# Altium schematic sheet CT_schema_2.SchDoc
size 287 x 169 mm
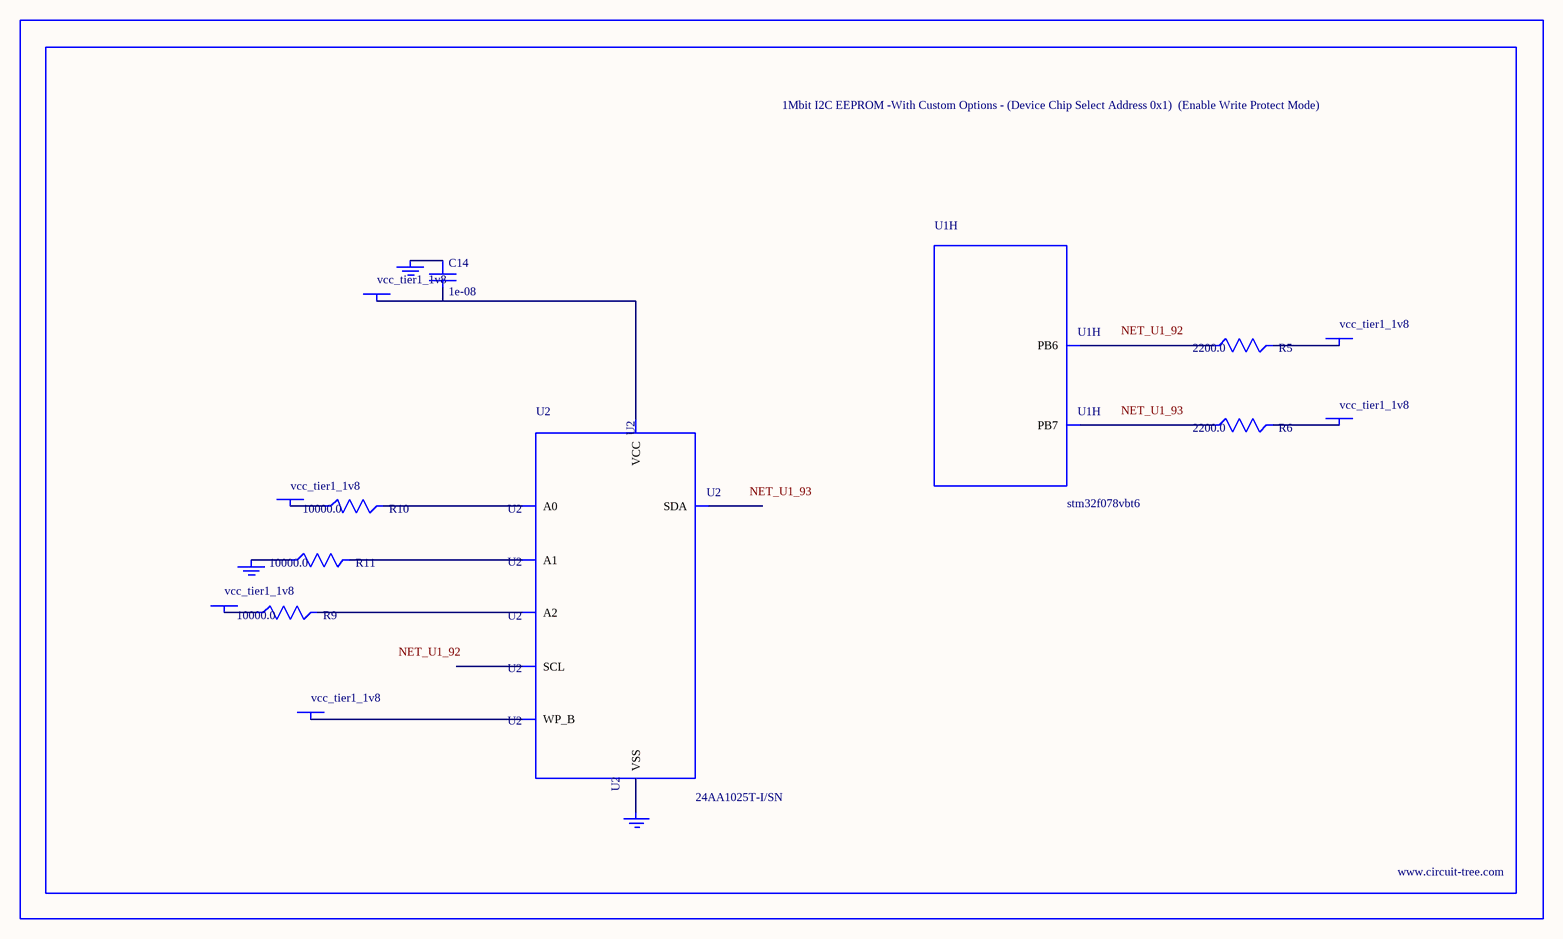
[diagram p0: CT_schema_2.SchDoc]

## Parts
BORDER1  (no value)
C14  1e-08  [C0402]
GND_INSTANCE_1_0  (no value)
GND_INSTANCE_1_1  (no value)
GND_INSTANCE_1_2  (no value)
POWER_INSTANCE_1_0  vcc_tier1_1v8
POWER_INSTANCE_1_1  vcc_tier1_1v8
POWER_INSTANCE_1_2  vcc_tier1_1v8
POWER_INSTANCE_1_3  vcc_tier1_1v8
POWER_INSTANCE_1_4  vcc_tier1_1v8
POWER_INSTANCE_1_5  vcc_tier1_1v8
R5  2200.0  [R0603]
R6  2200.0  [R0603]
R9  10000.0  [R0603]
R10  10000.0  [R0603]
R11  10000.0  [R0603]
U1  stm32f078vbt6  [LQFP100]  (part H of 9)
U2  24AA1025T-I/SN  [SOIC-8]

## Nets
NetC14_1: C14.1 GND_INSTANCE_1_1.0(GND)
NetC14_2: C14.2 POWER_INSTANCE_1_3.0(PWR) U2.8(VCC)
NetGND_INSTANCE_1_0_0: GND_INSTANCE_1_0.0(GND) R11.1
NetGND_INSTANCE_1_2_0: GND_INSTANCE_1_2.0(GND) U2.4(VSS)
NetPOWER_INSTANCE_1_0_0: POWER_INSTANCE_1_0.0(PWR) R10.1
NetPOWER_INSTANCE_1_1_0: POWER_INSTANCE_1_1.0(PWR) R9.1
NetPOWER_INSTANCE_1_2_0: POWER_INSTANCE_1_2.0(PWR) U2.7(WP_B)
NetPOWER_INSTANCE_1_4_0: POWER_INSTANCE_1_4.0(PWR) R5.2
NetPOWER_INSTANCE_1_5_0: POWER_INSTANCE_1_5.0(PWR) R6.2
NetR5_1: R5.1 U1.92(PB6)
NetR6_1: R6.1 U1.93(PB7)
NetR9_2: R9.2 U2.3(A2)
NetR10_2: R10.2 U2.1(A0)
NetR11_2: R11.2 U2.2(A1)

Not connected (* = marked no-connect by the designer): U2 5(SDA) 6(SCL)

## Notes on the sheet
- Labels drawn without touching a wire or pin: NET_U1_92, NET_U1_93

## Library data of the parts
BORDER1 = BORDER_PAGE1
C14 = C0402C103K3RAC
GND_INSTANCE_1_0-GND_INSTANCE_1_2 = GND
POWER_INSTANCE_1_0-POWER_INSTANCE_1_5 = PWR
R5 R6 = RC0603JR-072K2L
R9-R11 = RC0603JR-0710KL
